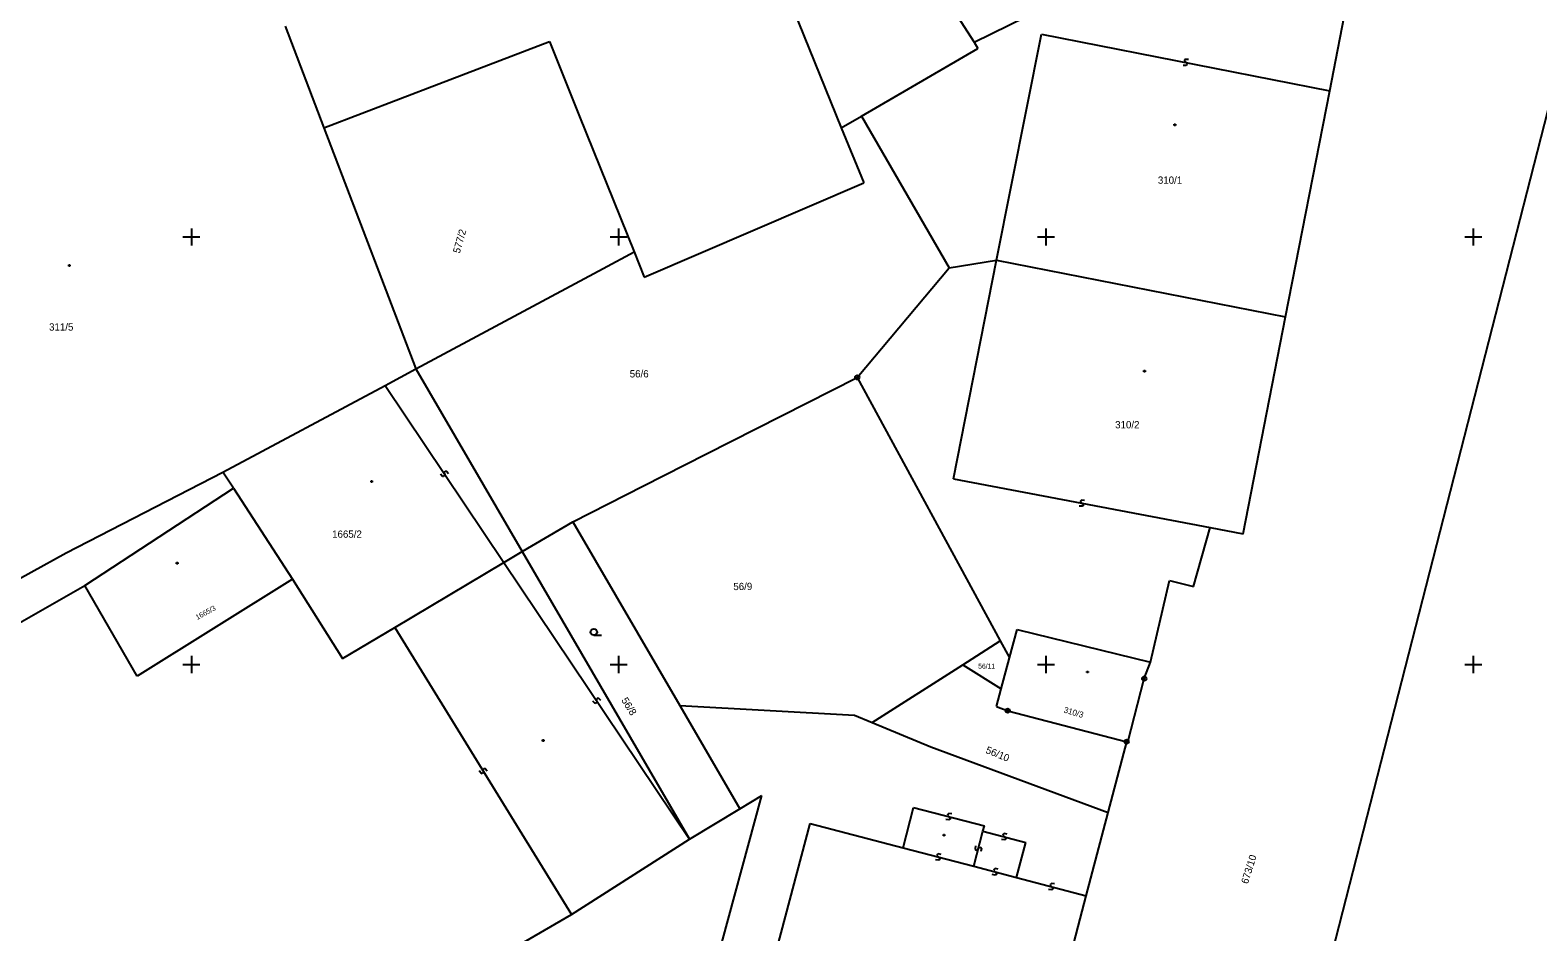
# Model space of a CAD drawing. Extents: x -492811 to -492366, y -1127107 to -1126748.
# Drawn here: x -492547.5 to -492477, y -1127032.5 to -1126990.3 of the extents above; entities that cross this region are included whole.
import ezdxf

# ---------------------------------------------------------------- set-up
doc = ezdxf.new("R2010")
doc.units = 0
doc.layers.add('katastrální mapa', color=7, linetype='Continuous')
doc.layers.add('síť', color=7, linetype='Continuous')

msp = doc.modelspace()

# ---------------------------------------------------------------- linework, layer by layer
at = {"layer": 'katastrální mapa'}
for p, q in [((-492526.22, -1126955.05), (-492503.36, -1126990.89)), ((-492518.07, -1126973.98), (-492509.58, -1126994.89)), ((-492486.71, -1126993.16), (-492485.35, -1126986.07)), ((-492535.61, -1126990.14), (-492533.8, -1126994.89)), ((-492503.36, -1126990.89), (-492500.91, -1126989.69)), ((-492528.41, -1126992.84), (-492523.24, -1126990.86)), ((-492523.24, -1126990.86), (-492521.83, -1126994.36)), ((-492503.36, -1126990.89), (-492503.19, -1126991.19)), ((-492502.32, -1127001.08), (-492500.2, -1126990.51)), ((-492500.2, -1126990.51), (-492486.71, -1126993.16)), ((-492508.64, -1126994.35), (-492503.19, -1126991.19)), ((-492493.44, -1126991.98), (-492493.58, -1126991.97)), ((-492493.51, -1126991.72), (-492493.52, -1126991.76)), ((-492493.52, -1126991.76), (-492493.49, -1126991.81)), ((-492493.47, -1126991.69), (-492493.51, -1126991.72)), ((-492493.49, -1126991.81), (-492493.42, -1126991.86)), ((-492493.33, -1126991.7), (-492493.47, -1126991.69)), ((-492493.4, -1126991.95), (-492493.44, -1126991.98)), ((-492493.42, -1126991.86), (-492493.39, -1126991.91)), ((-492493.39, -1126991.91), (-492493.4, -1126991.95)), ((-492533.8, -1126994.89), (-492528.41, -1126992.84)), ((-492493.64, -1127060.99), (-492476.34, -1126993.44)), ((-492488.79, -1127003.74), (-492486.71, -1126993.16)), ((-492521.83, -1126994.36), (-492519.27, -1127000.7)), ((-492509.58, -1126994.89), (-492508.64, -1126994.35)), ((-492508.64, -1126994.35), (-492504.53, -1127001.44)), ((-492533.8, -1126994.89), (-492530.77, -1127002.81)), ((-492509.58, -1126994.89), (-492508.53, -1126997.47)), ((-492493.99, -1126994.72), (-492493.93, -1126994.72)), ((-492493.99, -1126994.78), (-492493.99, -1126994.72)), ((-492493.93, -1126994.78), (-492493.99, -1126994.78)), ((-492493.93, -1126994.72), (-492493.93, -1126994.78)), ((-492518.8, -1127001.88), (-492508.53, -1126997.47)), ((-492520.73, -1127001.48), (-492519.27, -1127000.7)), ((-492519.27, -1127000.7), (-492518.8, -1127001.88)), ((-492545.74, -1127001.3), (-492545.68, -1127001.3)), ((-492545.74, -1127001.36), (-492545.74, -1127001.3)), ((-492545.68, -1127001.36), (-492545.74, -1127001.36)), ((-492545.68, -1127001.3), (-492545.68, -1127001.36)), ((-492529.49, -1127006.17), (-492520.73, -1127001.48)), ((-492508.83, -1127006.57), (-492504.53, -1127001.44)), ((-492504.53, -1127001.44), (-492502.32, -1127001.08)), ((-492504.32, -1127011.32), (-492502.32, -1127001.08)), ((-492502.32, -1127001.08), (-492488.79, -1127003.74)), ((-492530.77, -1127002.81), (-492529.49, -1127006.17)), ((-492490.77, -1127013.89), (-492488.79, -1127003.74)), ((-492530.93, -1127006.94), (-492529.49, -1127006.17)), ((-492529.49, -1127006.17), (-492524.51, -1127014.72)), ((-492495.42, -1127006.25), (-492495.36, -1127006.25)), ((-492495.42, -1127006.31), (-492495.42, -1127006.25)), ((-492495.36, -1127006.31), (-492495.42, -1127006.31)), ((-492495.36, -1127006.25), (-492495.36, -1127006.31)), ((-492538.52, -1127011), (-492530.93, -1127006.94)), ((-492530.93, -1127006.94), (-492525.37, -1127015.23)), ((-492515.92, -1127010.16), (-492508.83, -1127006.57)), ((-492508.83, -1127006.57), (-492502.14, -1127018.89)), ((-492518.84, -1127011.64), (-492515.92, -1127010.16)), ((-492545.86, -1127014.78), (-492538.52, -1127011)), ((-492538.03, -1127011.75), (-492538.52, -1127011)), ((-492528.24, -1127011.2), (-492528.34, -1127011.09)), ((-492528.19, -1127011.21), (-492528.24, -1127011.2)), ((-492528.16, -1127011.18), (-492528.19, -1127011.21)), ((-492528.14, -1127010.99), (-492528.16, -1127011.04)), ((-492528.16, -1127011.04), (-492528.14, -1127011.13)), ((-492528.14, -1127011.13), (-492528.16, -1127011.18)), ((-492528.11, -1127010.96), (-492528.14, -1127010.99)), ((-492528.06, -1127010.97), (-492528.11, -1127010.96)), ((-492527.96, -1127011.08), (-492528.06, -1127010.97)), ((-492504.32, -1127011.32), (-492492.31, -1127013.59)), ((-492544.99, -1127016.3), (-492538.03, -1127011.75)), ((-492538.03, -1127011.75), (-492535.26, -1127016)), ((-492531.59, -1127011.41), (-492531.53, -1127011.41)), ((-492531.59, -1127011.47), (-492531.59, -1127011.41)), ((-492531.53, -1127011.47), (-492531.59, -1127011.47)), ((-492531.53, -1127011.41), (-492531.53, -1127011.47)), ((-492522.14, -1127013.32), (-492518.84, -1127011.64)), ((-492498.3, -1127012.6), (-492498.44, -1127012.59)), ((-492498.33, -1127012.31), (-492498.38, -1127012.34)), ((-492498.38, -1127012.34), (-492498.38, -1127012.38)), ((-492498.38, -1127012.38), (-492498.35, -1127012.43)), ((-492498.35, -1127012.43), (-492498.28, -1127012.48)), ((-492498.19, -1127012.32), (-492498.33, -1127012.31)), ((-492498.25, -1127012.57), (-492498.3, -1127012.6)), ((-492498.28, -1127012.48), (-492498.25, -1127012.53)), ((-492498.25, -1127012.53), (-492498.25, -1127012.57)), ((-492524.51, -1127014.72), (-492522.14, -1127013.32)), ((-492522.14, -1127013.32), (-492517.14, -1127021.91)), ((-492493.1, -1127016.35), (-492492.31, -1127013.59)), ((-492492.31, -1127013.59), (-492490.77, -1127013.89)), ((-492550.27, -1127017.21), (-492545.86, -1127014.78)), ((-492525.37, -1127015.23), (-492524.51, -1127014.72)), ((-492524.51, -1127014.72), (-492516.68, -1127028.17)), ((-492540.69, -1127015.23), (-492540.63, -1127015.23)), ((-492540.69, -1127015.29), (-492540.69, -1127015.23)), ((-492540.63, -1127015.29), (-492540.69, -1127015.29)), ((-492540.63, -1127015.23), (-492540.63, -1127015.29)), ((-492530.48, -1127018.27), (-492525.37, -1127015.23)), ((-492525.37, -1127015.23), (-492516.68, -1127028.17)), ((-492550.66, -1127019.54), (-492544.99, -1127016.3)), ((-492542.54, -1127020.54), (-492544.99, -1127016.3)), ((-492535.26, -1127016), (-492542.54, -1127020.54)), ((-492535.26, -1127016), (-492532.92, -1127019.72)), ((-492495.11, -1127019.89), (-492494.21, -1127016.07)), ((-492494.21, -1127016.07), (-492493.1, -1127016.35)), ((-492532.92, -1127019.72), (-492530.48, -1127018.27)), ((-492530.48, -1127018.27), (-492522.21, -1127031.7)), ((-492501.71, -1127019.68), (-492501.35, -1127018.36)), ((-492501.35, -1127018.36), (-492495.11, -1127019.89)), ((-492521.16, -1127018.63), (-492520.81, -1127018.63)), ((-492503.89, -1127020.01), (-492502.14, -1127018.89)), ((-492502.14, -1127018.89), (-492501.71, -1127019.68)), ((-492502.1, -1127021.13), (-492501.71, -1127019.68)), ((-492508.13, -1127022.71), (-492503.89, -1127020.01)), ((-492503.89, -1127020.01), (-492502.1, -1127021.13)), ((-492498.08, -1127020.32), (-492498.02, -1127020.32)), ((-492498.08, -1127020.38), (-492498.08, -1127020.32)), ((-492498.02, -1127020.38), (-492498.08, -1127020.38)), ((-492498.02, -1127020.32), (-492498.02, -1127020.38)), ((-492495.4, -1127020.66), (-492495.11, -1127019.89)), ((-492502.32, -1127021.97), (-492502.1, -1127021.13)), ((-492496.17, -1127023.63), (-492495.4, -1127020.66)), ((-492521.12, -1127021.81), (-492521.21, -1127021.71)), ((-492521.06, -1127021.82), (-492521.12, -1127021.81)), ((-492521.03, -1127021.8), (-492521.06, -1127021.82)), ((-492521.02, -1127021.6), (-492521.03, -1127021.66)), ((-492521.03, -1127021.66), (-492521.02, -1127021.74)), ((-492521.02, -1127021.74), (-492521.03, -1127021.8)), ((-492520.99, -1127021.58), (-492521.02, -1127021.6)), ((-492520.93, -1127021.59), (-492520.99, -1127021.58)), ((-492520.84, -1127021.69), (-492520.93, -1127021.59)), ((-492517.14, -1127021.91), (-492508.96, -1127022.37)), ((-492517.14, -1127021.91), (-492514.32, -1127026.75)), ((-492508.96, -1127022.37), (-492508.13, -1127022.71)), ((-492502.32, -1127021.97), (-492501.79, -1127022.16)), ((-492501.79, -1127022.16), (-492496.22, -1127023.61)), ((-492508.13, -1127022.71), (-492505.38, -1127023.85)), ((-492523.56, -1127023.53), (-492523.5, -1127023.53)), ((-492523.56, -1127023.59), (-492523.56, -1127023.53)), ((-492523.5, -1127023.59), (-492523.56, -1127023.59)), ((-492523.5, -1127023.53), (-492523.5, -1127023.59)), ((-492505.38, -1127023.85), (-492497.09, -1127026.92)), ((-492497.09, -1127026.92), (-492496.22, -1127023.61)), ((-492496.22, -1127023.61), (-492496.17, -1127023.63)), ((-492526.44, -1127025.09), (-492526.53, -1127024.98)), ((-492526.39, -1127025.11), (-492526.44, -1127025.09)), ((-492526.35, -1127025.08), (-492526.39, -1127025.11)), ((-492526.34, -1127024.89), (-492526.35, -1127024.94)), ((-492526.35, -1127024.94), (-492526.34, -1127025.03)), ((-492526.34, -1127025.03), (-492526.35, -1127025.08)), ((-492526.3, -1127024.86), (-492526.34, -1127024.89)), ((-492526.25, -1127024.88), (-492526.3, -1127024.86)), ((-492526.16, -1127024.99), (-492526.25, -1127024.88)), ((-492517.2, -1127040.5), (-492513.29, -1127026.13)), ((-492514.32, -1127026.75), (-492513.29, -1127026.13)), ((-492516.68, -1127028.17), (-492514.32, -1127026.75)), ((-492506.69, -1127028.57), (-492506.2, -1127026.69)), ((-492506.2, -1127026.69), (-492502.88, -1127027.54)), ((-492512.59, -1127033.31), (-492511.04, -1127027.43)), ((-492511.04, -1127027.43), (-492506.69, -1127028.57)), ((-492504.54, -1127027.26), (-492504.68, -1127027.25)), ((-492504.59, -1127027), (-492504.6, -1127027.04)), ((-492504.6, -1127027.04), (-492504.57, -1127027.09)), ((-492504.54, -1127026.97), (-492504.59, -1127027)), ((-492504.57, -1127027.09), (-492504.51, -1127027.14)), ((-492504.4, -1127026.98), (-492504.54, -1127026.97)), ((-492504.49, -1127027.23), (-492504.54, -1127027.26)), ((-492504.51, -1127027.14), (-492504.48, -1127027.19)), ((-492504.48, -1127027.19), (-492504.49, -1127027.23)), ((-492502.95, -1127027.79), (-492502.88, -1127027.54)), ((-492498.11, -1127030.82), (-492497.09, -1127026.92)), ((-492522.21, -1127031.7), (-492516.68, -1127028.17)), ((-492504.8, -1127027.95), (-492504.74, -1127027.95)), ((-492504.8, -1127028.01), (-492504.8, -1127027.95)), ((-492504.74, -1127028.01), (-492504.8, -1127028.01)), ((-492504.74, -1127027.95), (-492504.74, -1127028.01)), ((-492503.38, -1127029.44), (-492502.95, -1127027.79)), ((-492502.95, -1127027.79), (-492500.94, -1127028.32)), ((-492501.94, -1127028.2), (-492502.08, -1127028.18)), ((-492502, -1127027.94), (-492502.01, -1127027.98)), ((-492502.01, -1127027.98), (-492501.98, -1127028.03)), ((-492501.95, -1127027.91), (-492502, -1127027.94)), ((-492501.98, -1127028.03), (-492501.91, -1127028.08)), ((-492501.81, -1127027.93), (-492501.95, -1127027.91)), ((-492501.89, -1127028.17), (-492501.94, -1127028.2)), ((-492501.91, -1127028.08), (-492501.88, -1127028.13)), ((-492501.88, -1127028.13), (-492501.89, -1127028.17)), ((-492506.69, -1127028.57), (-492503.38, -1127029.44)), ((-492505.09, -1127028.89), (-492505.1, -1127028.93)), ((-492505.1, -1127028.93), (-492505.07, -1127028.98)), ((-492505.04, -1127028.86), (-492505.09, -1127028.89)), ((-492505.07, -1127028.98), (-492505, -1127029.03)), ((-492504.9, -1127028.88), (-492505.04, -1127028.86)), ((-492503.29, -1127028.48), (-492503.31, -1127028.62)), ((-492503.31, -1127028.62), (-492503.28, -1127028.67)), ((-492503.28, -1127028.67), (-492503.24, -1127028.68)), ((-492503.24, -1127028.68), (-492503.19, -1127028.65)), ((-492503.19, -1127028.65), (-492503.14, -1127028.58)), ((-492503.14, -1127028.58), (-492503.09, -1127028.55)), ((-492503.09, -1127028.55), (-492503.05, -1127028.56)), ((-492503.05, -1127028.56), (-492503.02, -1127028.61)), ((-492503.02, -1127028.61), (-492503.04, -1127028.75)), ((-492501.37, -1127029.96), (-492500.94, -1127028.32)), ((-492505.03, -1127029.15), (-492505.17, -1127029.13)), ((-492504.98, -1127029.12), (-492505.03, -1127029.15)), ((-492505, -1127029.03), (-492504.97, -1127029.08)), ((-492504.97, -1127029.08), (-492504.98, -1127029.12)), ((-492503.38, -1127029.44), (-492501.37, -1127029.96)), ((-492502.43, -1127029.58), (-492502.44, -1127029.62)), ((-492502.44, -1127029.62), (-492502.41, -1127029.67)), ((-492502.38, -1127029.55), (-492502.43, -1127029.58)), ((-492502.41, -1127029.67), (-492502.34, -1127029.73)), ((-492502.24, -1127029.57), (-492502.38, -1127029.55)), ((-492502.37, -1127029.85), (-492502.51, -1127029.83)), ((-492502.32, -1127029.82), (-492502.37, -1127029.85)), ((-492502.34, -1127029.73), (-492502.31, -1127029.78)), ((-492502.31, -1127029.78), (-492502.32, -1127029.82)), ((-492501.37, -1127029.96), (-492498.11, -1127030.82)), ((-492499.79, -1127030.27), (-492499.8, -1127030.31)), ((-492499.8, -1127030.31), (-492499.77, -1127030.36)), ((-492499.74, -1127030.24), (-492499.79, -1127030.27)), ((-492499.77, -1127030.36), (-492499.71, -1127030.42)), ((-492499.6, -1127030.26), (-492499.74, -1127030.24)), ((-492499.71, -1127030.42), (-492499.68, -1127030.47)), ((-492501.71, -1127044.56), (-492498.11, -1127030.82)), ((-492499.74, -1127030.54), (-492499.88, -1127030.52)), ((-492499.69, -1127030.51), (-492499.74, -1127030.54)), ((-492499.68, -1127030.47), (-492499.69, -1127030.51)), ((-492534.75, -1127038.95), (-492522.21, -1127031.7))]:
    msp.add_line(p, q, dxfattribs=at)
for centre, radius in [((-492508.83, -1127006.57), 0.1), ((-492508.83, -1127006.57), 0.002), ((-492521.16, -1127018.48), 0.15), ((-492495.4, -1127020.66), 0.1), ((-492495.4, -1127020.66), 0.002), ((-492501.79, -1127022.16), 0.1), ((-492501.79, -1127022.16), 0.002), ((-492496.22, -1127023.61), 0.1), ((-492496.22, -1127023.61), 0.002)]:
    msp.add_circle(centre, radius, dxfattribs=at)
at = {"layer": 'síť'}
for p, q in [((-492540.4, -1127000), (-492539.6, -1127000)), ((-492540, -1126999.6), (-492540, -1127000.4)), ((-492520.4, -1127000), (-492519.6, -1127000)), ((-492520, -1126999.6), (-492520, -1127000.4)), ((-492500.4, -1127000), (-492499.6, -1127000)), ((-492500, -1126999.6), (-492500, -1127000.4)), ((-492480.4, -1127000), (-492479.6, -1127000)), ((-492480, -1126999.6), (-492480, -1127000.4)), ((-492540, -1127019.6), (-492540, -1127020.4)), ((-492520, -1127019.6), (-492520, -1127020.4)), ((-492500, -1127019.6), (-492500, -1127020.4)), ((-492480, -1127019.6), (-492480, -1127020.4)), ((-492540.4, -1127020), (-492539.6, -1127020)), ((-492520.4, -1127020), (-492519.6, -1127020)), ((-492500.4, -1127020), (-492499.6, -1127020)), ((-492480.4, -1127020), (-492479.6, -1127020))]:
    msp.add_line(p, q, dxfattribs=at)

# ---------------------------------------------------------------- texts
at = {"layer": 'katastrální mapa'}
for s, height, p in [('310/1', 0.34, (-492494.76, -1126997.51)), ('311/5', 0.34, (-492546.66, -1127004.38)), ('56/6', 0.34, (-492519.48, -1127006.57)), ('310/2', 0.34, (-492496.76, -1127008.95)), ('1665/2', 0.34, (-492533.41, -1127014.07)), ('56/11', 0.228, (-492503.17, -1127020.19))]:
    msp.add_text(s, height=height, dxfattribs=at).set_placement(p)
for s, height, rotation, p in [('577/2', 0.34, 73.971, (-492527.44, -1127000.79)), ('56/9', 0.34, 0.3348, (-492514.63, -1127016.52)), ('1665/3', 0.24, 28.8, (-492539.72, -1127017.92)), ('56/8', 0.34, 301.833, (-492519.89, -1127021.67)), ('310/3', 0.28, 343.719, (-492499.19, -1127022.24)), ('56/10', 0.34, 338.049, (-492502.85, -1127024.13)), ('673/10', 0.34, 72.594, (-492490.55, -1127030.29))]:
    msp.add_text(s, height=height, rotation=rotation, dxfattribs=at).set_placement(p)

doc.saveas('drawing.dxf')
